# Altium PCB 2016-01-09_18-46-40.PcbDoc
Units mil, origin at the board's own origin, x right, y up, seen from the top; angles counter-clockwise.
Board outline 7146 x 5717 mil, 4 copper layers (Top Layer, MidLayer1, MidLayer2, Bottom Layer); 1 components, 1 nets, 2 pads, 2 vias.
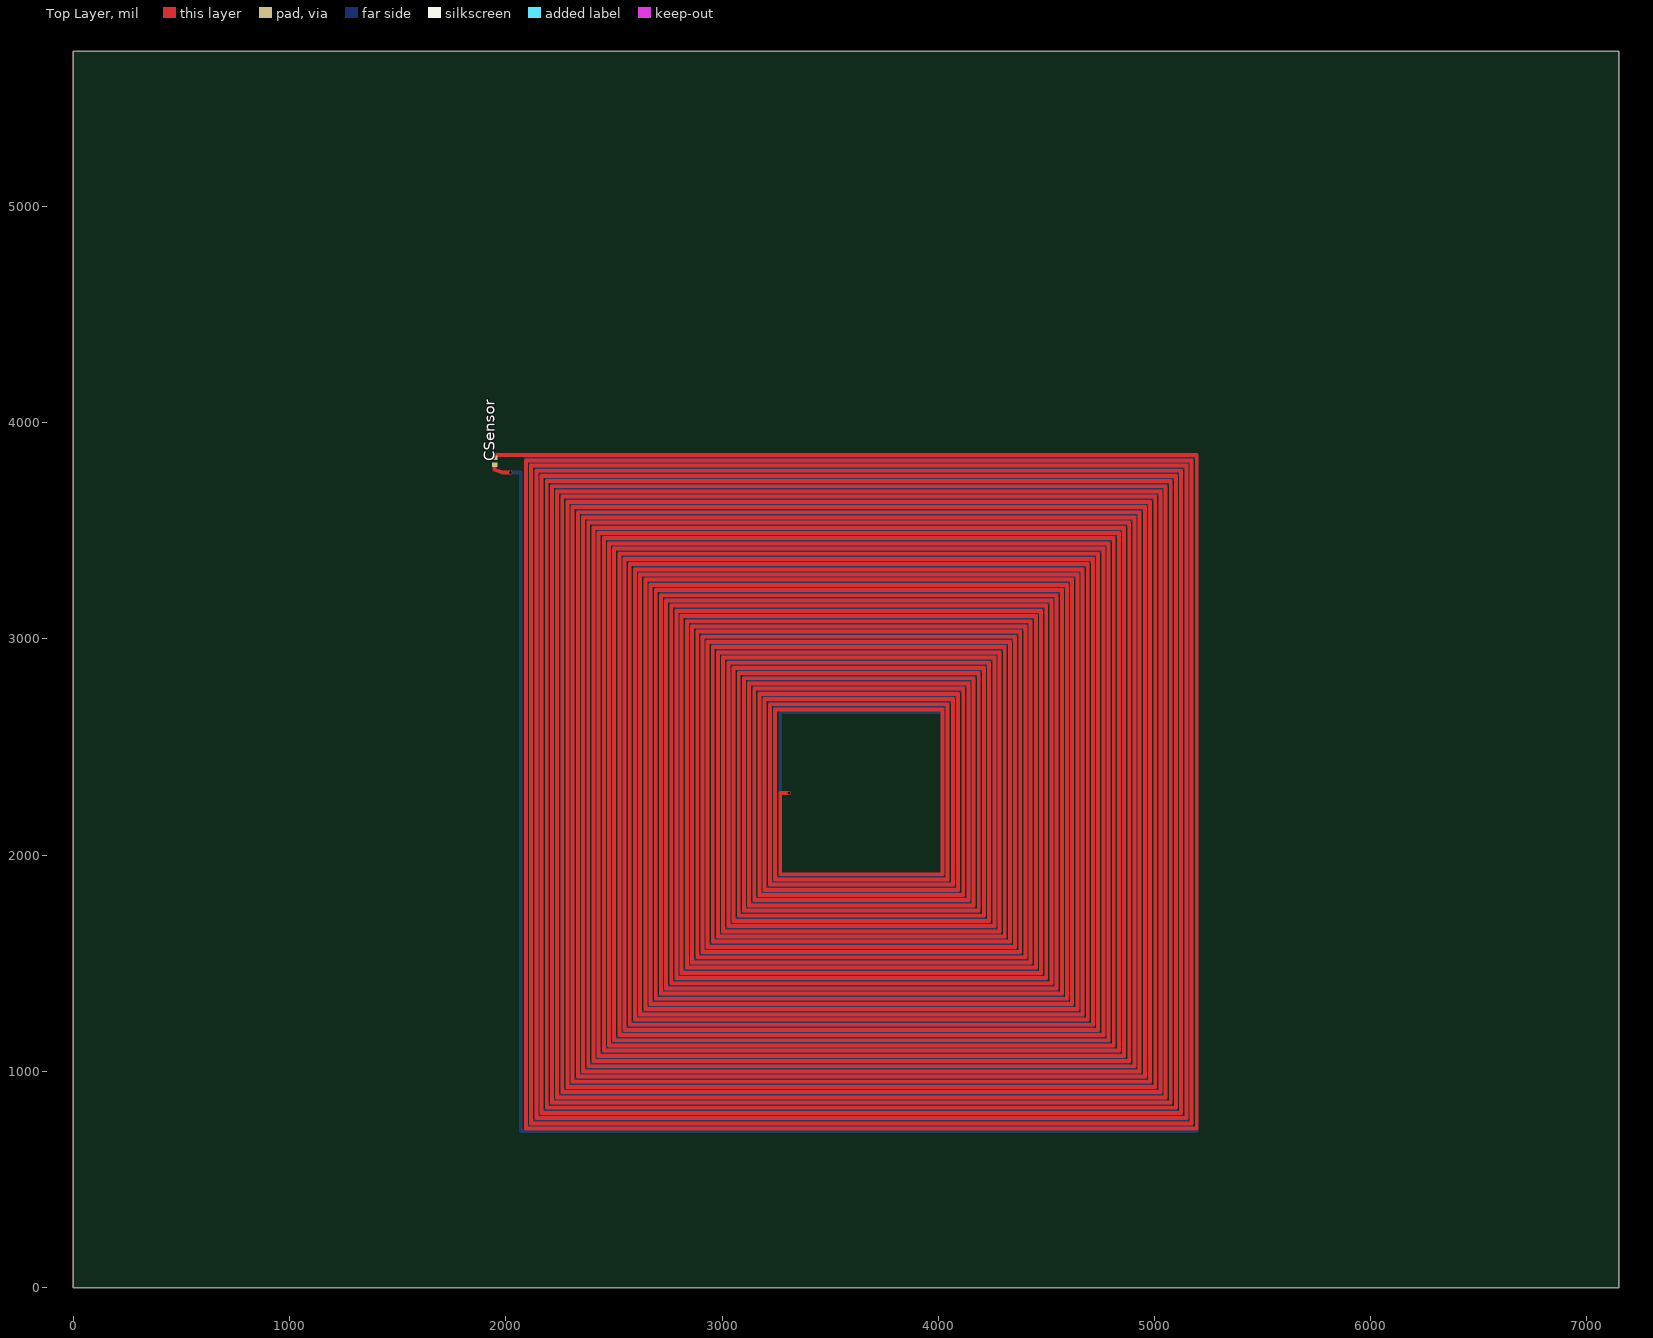
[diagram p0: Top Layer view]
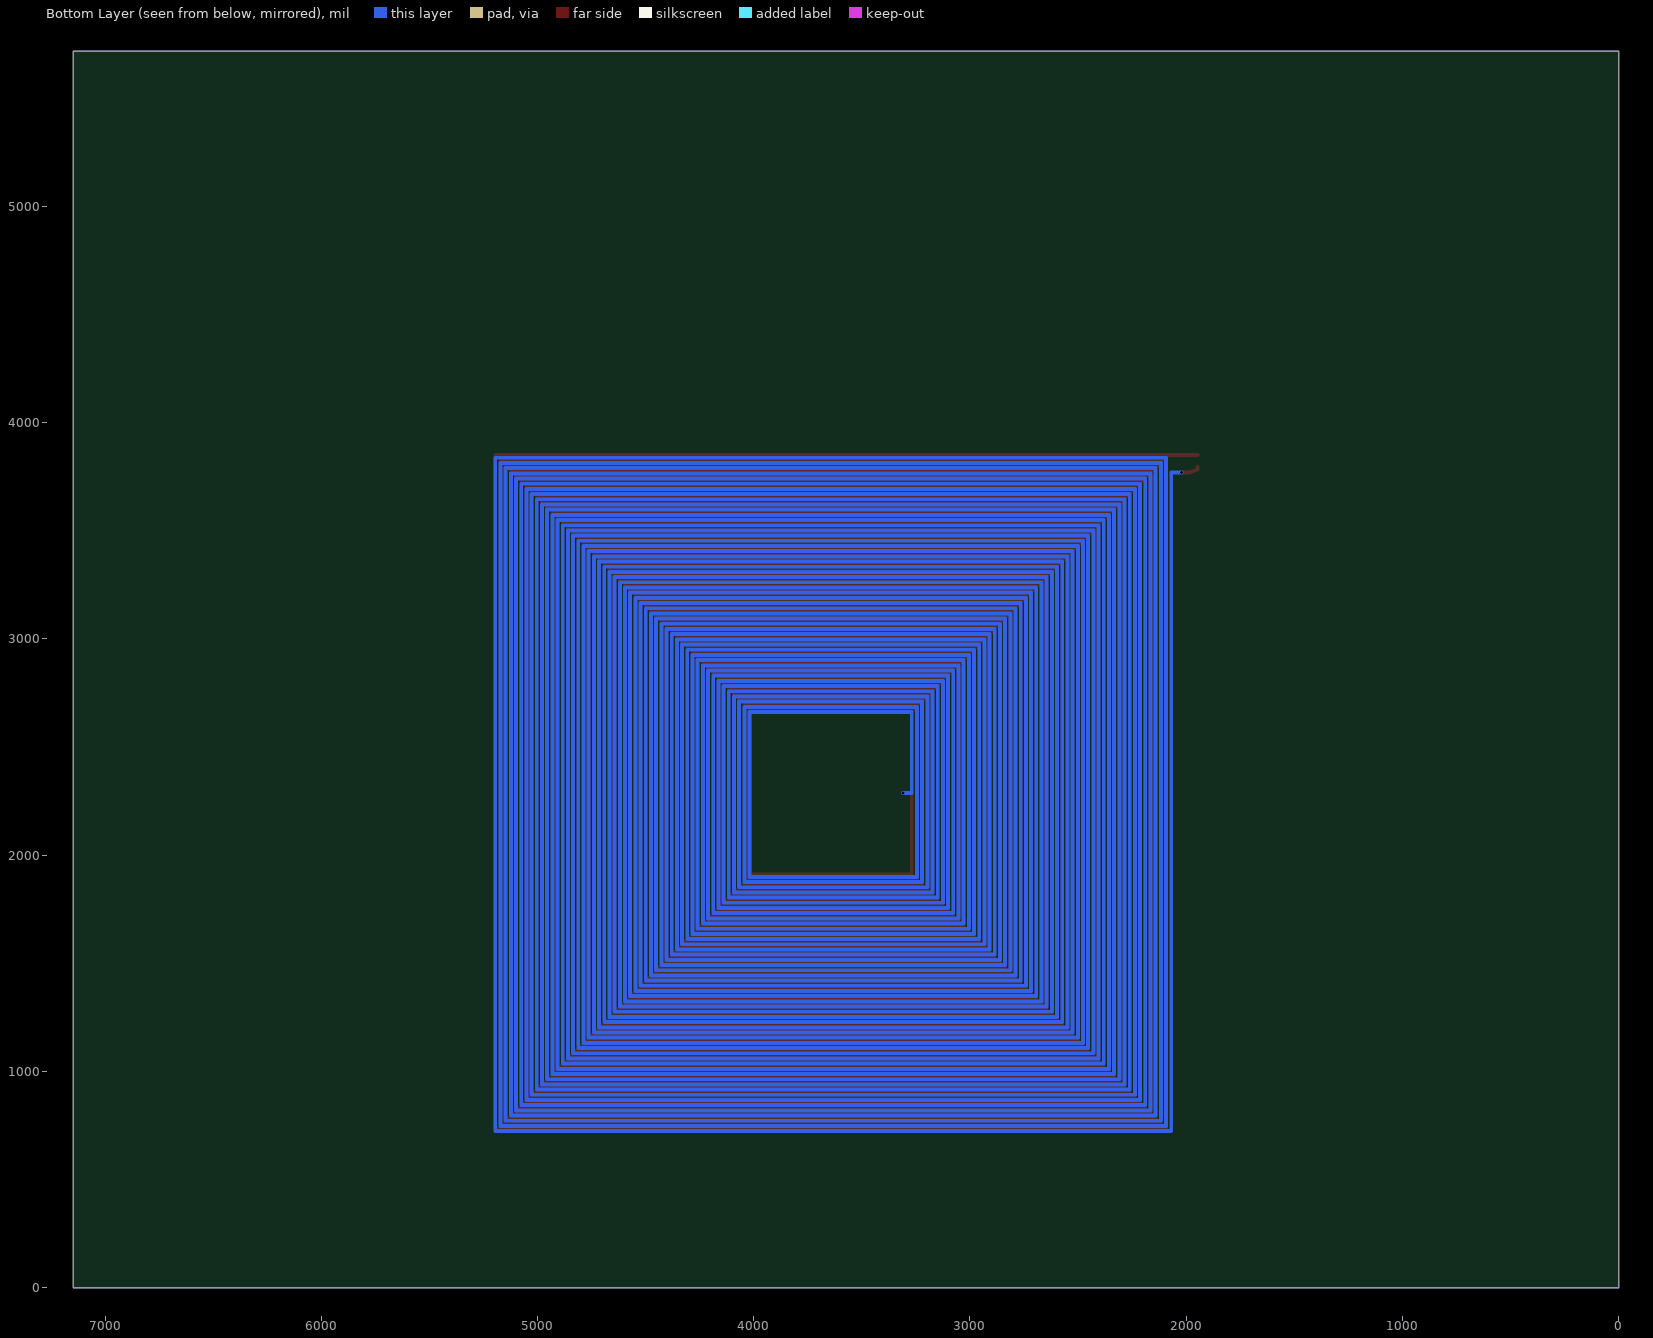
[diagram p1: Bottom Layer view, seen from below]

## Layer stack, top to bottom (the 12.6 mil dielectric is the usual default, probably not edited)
Top Layer: signal copper 1.4
Dielectric: core 12.6, FR-4, Dk 4.8
MidLayer1: signal copper 1.4
Dielectric: prepreg 12.6, FR-4, Dk 4.8
MidLayer2: signal copper 1.4
Dielectric: core 12.6, FR-4, Dk 4.8
Bottom Layer: signal copper 1.4

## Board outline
0,0 7146,0 7146,5717 0,5717

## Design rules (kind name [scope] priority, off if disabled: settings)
PlaneConnect [All] p0: scope1count=1 scope1_0_kind=Board scope1_0_value=Board scope2count=1 scope2_0_kind=Board scope2_0_value=Board commentlength=0 planeconnectstyle=Direct reliefexpansion=20 reliefentries=4 reliefconductorwidth=10 reliefairgap=10
PlaneConnect [All] p1: planeconnectstyle=Direct reliefexpansion=20 reliefentries=4 reliefconductorwidth=10 reliefairgap=10
PolygonConnect [All] p0: scope1count=1 scope1_0_kind=Board scope1_0_value=Board scope2count=1 scope2_0_kind=Board scope2_0_value=Board commentlength=0 connectstyle=Direct reliefconductorwidth=10 reliefentries=4 polygonreliefangle="90 Angle"
PolygonConnect [All] p1: connectstyle=Direct reliefconductorwidth=10 reliefentries=4 polygonreliefangle="90 Angle"

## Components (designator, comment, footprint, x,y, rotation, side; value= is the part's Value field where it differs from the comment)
CSensor "" 0402 1948,3822 r90 top

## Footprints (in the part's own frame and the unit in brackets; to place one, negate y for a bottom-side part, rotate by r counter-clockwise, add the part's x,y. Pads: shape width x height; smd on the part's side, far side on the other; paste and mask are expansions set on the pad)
0402 [mil]
  rect 22x24 smd: 1(-16.5,0) 2(16.5,0)

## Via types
v1: diameter 0, hole 14, Top Layer to Bottom Layer, 2 vias

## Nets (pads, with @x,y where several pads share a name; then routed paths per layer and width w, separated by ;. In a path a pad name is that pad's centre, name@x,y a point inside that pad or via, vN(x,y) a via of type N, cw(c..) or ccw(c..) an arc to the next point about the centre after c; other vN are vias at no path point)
3: CSensor.1 CSensor.2 | length 775591.7
  Top Layer w18: CSensor.1@1947.83,3794.97 1947.83,3782.47 1984.33,3769.97 2020.83,3769.97 ; 1947.83,3849.97 1984.33,3849.97 2020.83,3849.97 2044.83,3849.97 2068.83,3849.97 5195.17,3849.97 5195.17,735.63 2092.83,735.63 2092.83,3825.97 5171.17,3825.97 5171.17,759.63 2116.83,759.63 2116.83,3801.97 5147.17,3801.97 5147.17,783.63 2140.83,783.63 2140.83,3777.97 5123.17,3777.97 5123.17,807.63 2164.83,807.63 2164.83,3753.97 5099.17,3753.97 5099.17,831.63 2188.83,831.63 2188.83,3729.97 5075.17,3729.97 5075.17,855.63 2212.83,855.63 2212.83,3705.97 5051.17,3705.97 5051.17,879.63 2236.83,879.63 2236.83,3681.97 5027.17,3681.97 5027.17,903.63 2260.83,903.63 2260.83,3657.97 5003.17,3657.97 5003.17,927.63 2284.83,927.63 2284.83,3633.97 4979.17,3633.97 4979.17,951.63 2308.83,951.63 2308.83,3609.97 4955.17,3609.97 4955.17,975.63 2332.83,975.63 2332.83,3585.97 4931.17,3585.97 4931.17,999.63 2356.83,999.63 2356.83,3561.97 4907.17,3561.97 4907.17,1023.63 2380.83,1023.63 2380.83,3537.97 4883.17,3537.97 4883.17,1047.63 2404.83,1047.63 2404.83,3513.97 4859.17,3513.97 4859.17,1071.63 2428.83,1071.63 2428.83,3489.97 4835.17,3489.97 4835.17,1095.63 2452.83,1095.63 2452.83,3465.97 4811.17,3465.97 4811.17,1119.63 2476.83,1119.63 2476.83,3441.97 4787.17,3441.97 4787.17,1143.63 2500.83,1143.63 2500.83,3417.97 4763.17,3417.97 4763.17,1167.63 2524.83,1167.63 2524.83,3393.97 4739.17,3393.97 4739.17,1191.63 2548.83,1191.63 2548.83,3369.97 4715.17,3369.97 4715.17,1215.63 2572.83,1215.63 2572.83,3345.97 4691.17,3345.97 4691.17,1239.63 2596.83,1239.63 2596.83,3321.97 4667.17,3321.97 4667.17,1263.63 2620.83,1263.63 2620.83,3297.97 4643.17,3297.97 4643.17,1287.63 2644.83,1287.63 2644.83,3273.97 4619.17,3273.97 4619.17,1311.63 2668.83,1311.63 2668.83,3249.97 4595.17,3249.97 4595.17,1335.63 2692.83,1335.63 2692.83,3225.97 4571.17,3225.97 4571.17,1359.63 2716.83,1359.63 2716.83,3201.97 4547.17,3201.97 4547.17,1383.63 2740.83,1383.63 2740.83,3177.97 4523.17,3177.97 4523.17,1407.63 2764.83,1407.63 2764.83,3153.97 4499.17,3153.97 4499.17,1431.63 2788.83,1431.63 2788.83,3129.97 4475.17,3129.97 4475.17,1455.63 2812.83,1455.63 2812.83,3105.97 4451.17,3105.97 4451.17,1479.63 2836.83,1479.63 2836.83,3081.97 4427.17,3081.97 4427.17,1503.63 2860.83,1503.63 2860.83,3057.97 4403.17,3057.97 4403.17,1527.63 2884.83,1527.63 2884.83,3033.97 4379.17,3033.97 4379.17,1551.63 2908.83,1551.63 2908.83,3009.97 4355.17,3009.97 4355.17,1575.63 2932.83,1575.63 2932.83,2985.97 4331.17,2985.97 4331.17,1599.63 2956.83,1599.63 2956.83,2961.97 4307.17,2961.97 4307.17,1623.63 2980.83,1623.63 2980.83,2937.97 4283.17,2937.97 4283.17,1647.63 3004.83,1647.63 3004.83,2913.97 4259.17,2913.97 4259.17,1671.63 3028.83,1671.63 3028.83,2889.97 4235.17,2889.97 4235.17,1695.63 3052.83,1695.63 3052.83,2865.97 4211.17,2865.97 4211.17,1719.63 3076.83,1719.63 3076.83,2841.97 4187.17,2841.97 4187.17,1743.63 3100.83,1743.63 3100.83,2817.97 4163.17,2817.97 4163.17,1767.63 3124.83,1767.63 3124.83,2793.97 4139.17,2793.97 4139.17,1791.63 3148.83,1791.63 3148.83,2769.97 4115.17,2769.97 4115.17,1815.63 3172.83,1815.63 3172.83,2745.97 4091.17,2745.97 4091.17,1839.63 3196.83,1839.63 3196.83,2721.97 4067.17,2721.97 4067.17,1863.63 3220.83,1863.63 3220.83,2697.97 4043.17,2697.97 4043.17,1887.63 3244.83,1887.63 3244.83,2673.97 4019.17,2673.97 4019.17,1911.63 3268.83,1911.63 3268.83,2286.8 3288.83,2286.8 3308.83,2286.8
  Bottom Layer w18: 2020.83,3769.97 2044.83,3769.97 2068.83,3769.97 2068.83,723.63 5195.17,723.63 5195.17,3837.97 2092.83,3837.97 2092.83,747.63 5171.17,747.63 5171.17,3813.97 2116.83,3813.97 2116.83,771.63 5147.17,771.63 5147.17,3789.97 2140.83,3789.97 2140.83,795.63 5123.17,795.63 5123.17,3765.97 2164.83,3765.97 2164.83,819.63 5099.17,819.63 5099.17,3741.97 2188.83,3741.97 2188.83,843.63 5075.17,843.63 5075.17,3717.97 2212.83,3717.97 2212.83,867.63 5051.17,867.63 5051.17,3693.97 2236.83,3693.97 2236.83,891.63 5027.17,891.63 5027.17,3669.97 2260.83,3669.97 2260.83,915.63 5003.17,915.63 5003.17,3645.97 2284.83,3645.97 2284.83,939.63 4979.17,939.63 4979.17,3621.97 2308.83,3621.97 2308.83,963.63 4955.17,963.63 4955.17,3597.97 2332.83,3597.97 2332.83,987.63 4931.17,987.63 4931.17,3573.97 2356.83,3573.97 2356.83,1011.63 4907.17,1011.63 4907.17,3549.97 2380.83,3549.97 2380.83,1035.63 4883.17,1035.63 4883.17,3525.97 2404.83,3525.97 2404.83,1059.63 4859.17,1059.63 4859.17,3501.97 2428.83,3501.97 2428.83,1083.63 4835.17,1083.63 4835.17,3477.97 2452.83,3477.97 2452.83,1107.63 4811.17,1107.63 4811.17,3453.97 2476.83,3453.97 2476.83,1131.63 4787.17,1131.63 4787.17,3429.97 2500.83,3429.97 2500.83,1155.63 4763.17,1155.63 4763.17,3405.97 2524.83,3405.97 2524.83,1179.63 4739.17,1179.63 4739.17,3381.97 2548.83,3381.97 2548.83,1203.63 4715.17,1203.63 4715.17,3357.97 2572.83,3357.97 2572.83,1227.63 4691.17,1227.63 4691.17,3333.97 2596.83,3333.97 2596.83,1251.63 4667.17,1251.63 4667.17,3309.97 2620.83,3309.97 2620.83,1275.63 4643.17,1275.63 4643.17,3285.97 2644.83,3285.97 2644.83,1299.63 4619.17,1299.63 4619.17,3261.97 2668.83,3261.97 2668.83,1323.63 4595.17,1323.63 4595.17,3237.97 2692.83,3237.97 2692.83,1347.63 4571.17,1347.63 4571.17,3213.97 2716.83,3213.97 2716.83,1371.63 4547.17,1371.63 4547.17,3189.97 2740.83,3189.97 2740.83,1395.63 4523.17,1395.63 4523.17,3165.97 2764.83,3165.97 2764.83,1419.63 4499.17,1419.63 4499.17,3141.97 2788.83,3141.97 2788.83,1443.63 4475.17,1443.63 4475.17,3117.97 2812.83,3117.97 2812.83,1467.63 4451.17,1467.63 4451.17,3093.97 2836.83,3093.97 2836.83,1491.63 4427.17,1491.63 4427.17,3069.97 2860.83,3069.97 2860.83,1515.63 4403.17,1515.63 4403.17,3045.97 2884.83,3045.97 2884.83,1539.63 4379.17,1539.63 4379.17,3021.97 2908.83,3021.97 2908.83,1563.63 4355.17,1563.63 4355.17,2997.97 2932.83,2997.97 2932.83,1587.63 4331.17,1587.63 4331.17,2973.97 2956.83,2973.97 2956.83,1611.63 4307.17,1611.63 4307.17,2949.97 2980.83,2949.97 2980.83,1635.63 4283.17,1635.63 4283.17,2925.97 3004.83,2925.97 3004.83,1659.63 4259.17,1659.63 4259.17,2901.97 3028.83,2901.97 3028.83,1683.63 4235.17,1683.63 4235.17,2877.97 3052.83,2877.97 3052.83,1707.63 4211.17,1707.63 4211.17,2853.97 3076.83,2853.97 3076.83,1731.63 4187.17,1731.63 4187.17,2829.97 3100.83,2829.97 3100.83,1755.63 4163.17,1755.63 4163.17,2805.97 3124.83,2805.97 3124.83,1779.63 4139.17,1779.63 4139.17,2781.97 3148.83,2781.97 3148.83,1803.63 4115.17,1803.63 4115.17,2757.97 3172.83,2757.97 3172.83,1827.63 4091.17,1827.63 4091.17,2733.97 3196.83,2733.97 3196.83,1851.63 4067.17,1851.63 4067.17,2709.97 3220.83,2709.97 3220.83,1875.63 4043.17,1875.63 4043.17,2685.97 3244.83,2685.97 3244.83,1899.63 4019.17,1899.63 4019.17,2661.97 3268.83,2661.97 3268.83,2286.8 3288.83,2286.8 3308.83,2286.8
  other v1: 3309,2287 2021,3770

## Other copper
Multi-Layer:
  the board outline again, w1
  text "Exported from WEBENCH Coil Designer Tool" at 813,5362 h138
  text "WEBENCH Design Information" at 107,5069 h86
  text "Coil Parameters" at 4126,5043 h86
  text "-------------------------" at 107,4957 h86
  text "--------------" at 4126,4931 h86
  text "User Id - 3988952" at 107,4845 h86
  text "Layers = 2" at 4126,4820 h86
  text "Design Id - 11" at 107,4734 h86
  text "Turns = 50" at 4126,4708 h86
  text "Exported on - 2016/01/09 18:46:38" at 107,4622 h86
  text "Trace Width = 18.0 mils" at 4126,4596 h86
  text "Version - 1.0" at 107,4510 h86
  text "Trace Spacing = 6.0 mils" at 4126,4484 h86
  text "Inner Diameter = 738 mils (Approx.)" at 4126,4372 h86
  text "Outer Diameter = 3138 mils (Approx.)" at 4126,4261 h86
